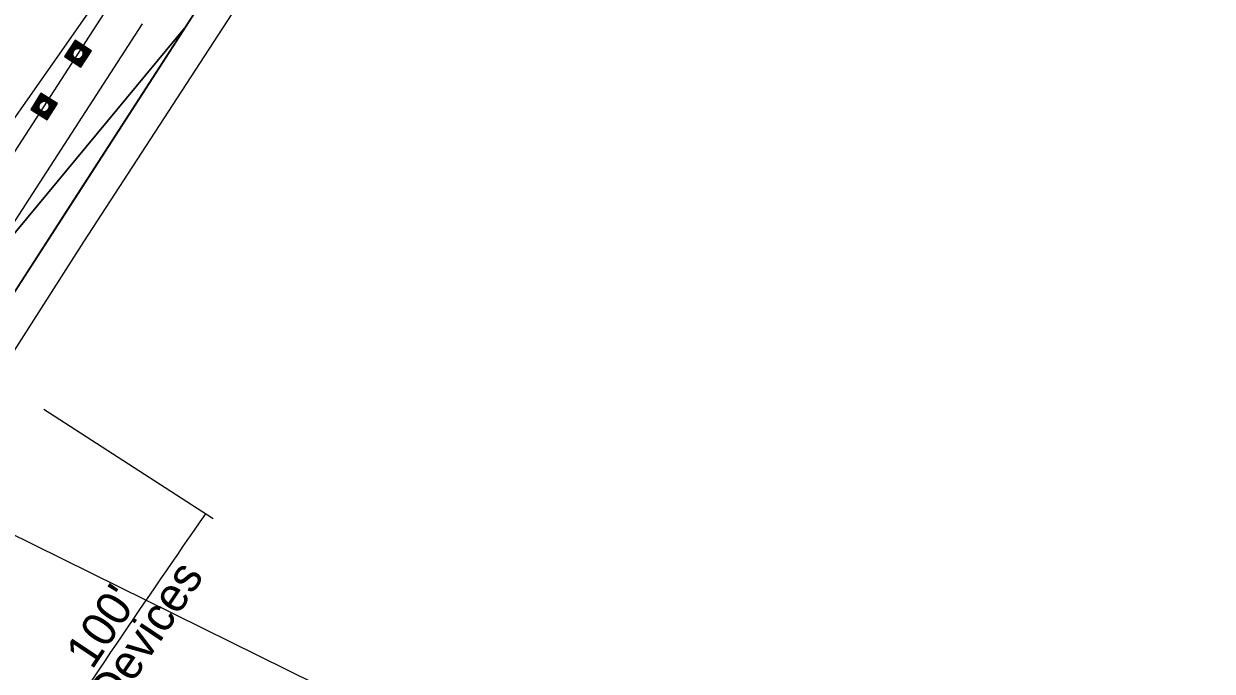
# Model space of a CAD drawing. Extents: x 14104283 to 14128447, y 8633203 to 8671666.
# Drawn here: x 14119316 to 14119692.1, y 8668955.5 to 8669160.5 of the extents above; entities that cross this region are included whole.
import ezdxf

# ---------------------------------------------------------------- set-up
doc = ezdxf.new("R2010")
doc.units = 0
for name, color, linetype in [('dsnCellElements', 7, 'Continuous'), ('dsnNonPlotable', 7, 'Continuous'), ('dsnPaintExistingBrokenLaneLineWhite', 7, 'Continuous'), ('dsnPaintExistingEdgeLineRightWhite', 7, 'Continuous'), ('dsnShadingPaved', 7, 'Continuous'), ('dsnStdLabel', 7, 'Continuous'), ('dsnStgShadingPrevPav', 7, 'Continuous'), ('dsnTapeExistingChannelizingLaneYellow', 7, 'Continuous'), ('dsnTapePlaceChannelizingYellow', 7, 'Continuous'), ('dsnTapeRemoveChannelizingWhite', 7, 'Continuous')]:
    doc.layers.add(name, color=color, linetype=linetype)

msp = doc.modelspace()

# ---------------------------------------------------------------- linework, layer by layer
at = {"layer": 'dsnCellElements'}
for centre in [(14119333.18, 8669150.98), (14119322.46, 8669134.28)]:
    msp.add_circle(centre, 1.65, dxfattribs=at)
at = {"layer": 'dsnNonPlotable'}
msp.add_lwpolyline([(14118092.03, 8667853.71), (14118786.76, 8669258.84), (14119692.14, 8668811.2), (14118997.41, 8667406.07)], close=True, dxfattribs=at)
at = {"layer": 'dsnPaintExistingBrokenLaneLineWhite'}
msp.add_line((14119234.39, 8668975.91), (14119353.59, 8669160.47), dxfattribs=at)
at = {"layer": 'dsnPaintExistingEdgeLineRightWhite'}
for p, q in [((14119329.79, 8669101.47), (14119537.52, 8669423.28)), ((14119259.6, 8668992.73), (14119329.79, 8669101.47))]:
    msp.add_line(p, q, dxfattribs=at)
at = {"layer": 'dsnShadingPaved'}
for p, q in [((14119403.44, 8669259.76), (14119219.81, 8668997.42)), ((14119292.6, 8669088.16), (14119403.44, 8669259.76)), ((14119415.05, 8669233.56), (14119367.38, 8669159.7)), ((14119367.38, 8669159.7), (14119244.61, 8668969.51)), ((14119367.38, 8669159.7), (14119302.7, 8669081.64)), ((14119302.7, 8669081.64), (14119367.38, 8669159.7))]:
    msp.add_line(p, q, dxfattribs=at)
at = {"layer": 'dsnStdLabel'}
msp.add_line((14119375.93, 8669003.77), (14119322.35, 8669038.36), dxfattribs=at)
for points in [[(14119334.06, 8669146.74), (14119337.42, 8669151.86), (14119332.29, 8669155.22), (14119328.94, 8669150.09), (14119334.06, 8669146.74)], [(14119334.06, 8669146.74), (14119337.41, 8669151.86), (14119332.29, 8669155.21), (14119328.94, 8669150.09), (14119334.06, 8669146.74)], [(14119334.06, 8669146.74), (14119337.41, 8669151.86), (14119332.29, 8669155.21), (14119328.94, 8669150.09), (14119334.06, 8669146.74)], [(14119334.1, 8669146.87), (14119337.36, 8669151.85), (14119332.3, 8669155.16), (14119328.99, 8669150.1), (14119334.08, 8669146.77)], [(14119334.09, 8669146.92), (14119337.32, 8669151.84), (14119332.31, 8669155.11), (14119329.04, 8669150.11), (14119334.1, 8669146.8)], [(14119334.08, 8669146.96), (14119337.27, 8669151.83), (14119332.32, 8669155.07), (14119329.08, 8669150.12), (14119334.12, 8669146.82)], [(14119334.08, 8669147.01), (14119337.22, 8669151.82), (14119332.33, 8669155.02), (14119329.13, 8669150.13), (14119334.1, 8669146.87)], [(14119334.07, 8669147.06), (14119337.18, 8669151.81), (14119332.34, 8669154.98), (14119329.17, 8669150.14), (14119334.09, 8669146.92)], [(14119334.06, 8669147.1), (14119337.13, 8669151.8), (14119332.35, 8669154.93), (14119329.22, 8669150.15), (14119334.08, 8669146.96)], [(14119334.05, 8669147.15), (14119337.09, 8669151.79), (14119332.36, 8669154.89), (14119329.26, 8669150.16), (14119334.08, 8669147.01)], [(14119334.04, 8669147.19), (14119337.04, 8669151.78), (14119332.37, 8669154.84), (14119329.31, 8669150.17), (14119334.07, 8669147.06)], [(14119334.03, 8669147.24), (14119337, 8669151.77), (14119332.38, 8669154.79), (14119329.36, 8669150.18), (14119334.06, 8669147.1)], [(14119334.02, 8669147.28), (14119336.95, 8669151.76), (14119332.39, 8669154.75), (14119329.4, 8669150.19), (14119334.05, 8669147.15)], [(14119334.01, 8669147.33), (14119336.9, 8669151.75), (14119332.4, 8669154.7), (14119329.45, 8669150.2), (14119334.04, 8669147.19)], [(14119334, 8669147.38), (14119336.86, 8669151.74), (14119332.41, 8669154.66), (14119329.49, 8669150.21), (14119334.03, 8669147.24)], [(14119333.99, 8669147.42), (14119336.81, 8669151.73), (14119332.42, 8669154.61), (14119329.54, 8669150.22), (14119334.02, 8669147.28)], [(14119333.98, 8669147.47), (14119336.77, 8669151.72), (14119332.43, 8669154.57), (14119329.58, 8669150.23), (14119334.01, 8669147.33)], [(14119333.97, 8669147.51), (14119336.72, 8669151.72), (14119332.44, 8669154.52), (14119329.63, 8669150.23), (14119334, 8669147.38)], [(14119333.96, 8669147.56), (14119336.68, 8669151.71), (14119332.44, 8669154.48), (14119329.68, 8669150.24), (14119333.99, 8669147.42)], [(14119333.95, 8669147.6), (14119336.63, 8669151.7), (14119332.45, 8669154.43), (14119329.72, 8669150.25), (14119333.98, 8669147.47)], [(14119333.94, 8669147.65), (14119336.58, 8669151.69), (14119332.46, 8669154.38), (14119329.77, 8669150.26), (14119333.97, 8669147.51)], [(14119333.93, 8669147.69), (14119336.54, 8669151.68), (14119332.47, 8669154.34), (14119329.81, 8669150.27), (14119333.96, 8669147.56)], [(14119333.92, 8669147.74), (14119336.49, 8669151.67), (14119332.48, 8669154.29), (14119329.86, 8669150.28), (14119333.95, 8669147.6)], [(14119333.91, 8669147.79), (14119336.45, 8669151.66), (14119332.49, 8669154.25), (14119329.9, 8669150.29), (14119333.94, 8669147.65)], [(14119333.9, 8669147.83), (14119336.4, 8669151.65), (14119332.5, 8669154.2), (14119329.95, 8669150.3), (14119333.93, 8669147.69)], [(14119333.89, 8669147.88), (14119336.36, 8669151.64), (14119332.51, 8669154.16), (14119330, 8669150.31), (14119333.92, 8669147.74)], [(14119333.88, 8669147.92), (14119336.31, 8669151.63), (14119332.52, 8669154.11), (14119330.04, 8669150.32), (14119333.91, 8669147.79)], [(14119333.87, 8669147.97), (14119336.26, 8669151.62), (14119332.53, 8669154.06), (14119330.09, 8669150.33), (14119333.9, 8669147.83)], [(14119333.87, 8669148.01), (14119336.22, 8669151.61), (14119332.54, 8669154.02), (14119330.13, 8669150.34), (14119333.89, 8669147.88)], [(14119333.86, 8669148.06), (14119336.17, 8669151.6), (14119332.55, 8669153.97), (14119330.18, 8669150.35), (14119333.88, 8669147.92)], [(14119333.85, 8669148.11), (14119336.13, 8669151.59), (14119332.56, 8669153.93), (14119330.22, 8669150.36), (14119333.87, 8669147.97)], [(14119333.84, 8669148.15), (14119336.08, 8669151.58), (14119332.57, 8669153.88), (14119330.27, 8669150.37), (14119333.87, 8669148.01)], [(14119333.83, 8669148.2), (14119336.04, 8669151.57), (14119332.58, 8669153.84), (14119330.32, 8669150.38), (14119333.86, 8669148.06)], [(14119333.82, 8669148.24), (14119335.99, 8669151.56), (14119332.59, 8669153.79), (14119330.36, 8669150.39), (14119333.85, 8669148.11)], [(14119333.81, 8669148.29), (14119335.94, 8669151.55), (14119332.6, 8669153.74), (14119330.41, 8669150.4), (14119333.84, 8669148.15)], [(14119333.8, 8669148.33), (14119335.9, 8669151.54), (14119332.61, 8669153.7), (14119330.45, 8669150.41), (14119333.83, 8669148.2)], [(14119333.79, 8669148.38), (14119335.85, 8669151.53), (14119332.62, 8669153.65), (14119330.5, 8669150.42), (14119333.82, 8669148.24)], [(14119333.78, 8669148.43), (14119335.81, 8669151.52), (14119332.63, 8669153.61), (14119330.54, 8669150.43), (14119333.81, 8669148.29)], [(14119333.77, 8669148.47), (14119335.76, 8669151.52), (14119332.64, 8669153.56), (14119330.59, 8669150.44), (14119333.8, 8669148.33)], [(14119333.76, 8669148.52), (14119335.72, 8669151.51), (14119332.65, 8669153.52), (14119330.64, 8669150.44), (14119333.79, 8669148.38)], [(14119333.75, 8669148.56), (14119335.67, 8669151.5), (14119332.65, 8669153.47), (14119330.68, 8669150.45), (14119333.78, 8669148.43)], [(14119333.74, 8669148.61), (14119335.62, 8669151.49), (14119332.66, 8669153.42), (14119330.73, 8669150.46), (14119333.77, 8669148.47)], [(14119333.73, 8669148.65), (14119335.58, 8669151.48), (14119332.67, 8669153.38), (14119330.77, 8669150.47), (14119333.76, 8669148.52)], [(14119333.72, 8669148.7), (14119335.53, 8669151.47), (14119332.68, 8669153.33), (14119330.82, 8669150.48), (14119333.75, 8669148.56)], [(14119333.71, 8669148.75), (14119335.49, 8669151.46), (14119332.69, 8669153.29), (14119330.86, 8669150.49), (14119333.74, 8669148.61)], [(14119333.7, 8669148.79), (14119335.44, 8669151.45), (14119332.7, 8669153.24), (14119330.91, 8669150.5), (14119333.73, 8669148.65)], [(14119331.66, 8669151.6), (14119330.95, 8669150.51), (14119332.04, 8669149.8)], [(14119331.62, 8669151.46), (14119331, 8669150.52), (14119331.94, 8669149.91)], [(14119331.59, 8669151.36), (14119331.05, 8669150.53), (14119331.87, 8669149.99)], [(14119331.57, 8669151.27), (14119331.09, 8669150.54), (14119331.82, 8669150.06)], [(14119331.56, 8669151.19), (14119331.14, 8669150.55), (14119331.78, 8669150.13)], [(14119331.55, 8669151.12), (14119331.18, 8669150.56), (14119331.74, 8669150.19)], [(14119331.54, 8669151.05), (14119331.23, 8669150.57), (14119331.71, 8669150.25)], [(14119331.54, 8669150.99), (14119331.27, 8669150.58), (14119331.68, 8669150.31)], [(14119331.54, 8669150.93), (14119331.32, 8669150.59), (14119331.66, 8669150.37)], [(14119331.55, 8669150.87), (14119331.37, 8669150.6), (14119331.64, 8669150.42)], [(14119331.55, 8669150.82), (14119331.41, 8669150.61), (14119331.62, 8669150.47)], [(14119331.56, 8669150.77), (14119331.46, 8669150.62), (14119331.61, 8669150.52)], [(14119331.56, 8669150.72), (14119331.5, 8669150.63), (14119331.59, 8669150.57)], [(14119331.57, 8669150.67), (14119331.55, 8669150.64), (14119331.58, 8669150.61)], [(14119333.8, 8669152.49), (14119332.71, 8669153.2), (14119332, 8669152.11)], [(14119333.66, 8669152.53), (14119332.72, 8669153.15), (14119332.11, 8669152.21)], [(14119333.56, 8669152.56), (14119332.73, 8669153.1), (14119332.19, 8669152.28)], [(14119333.47, 8669152.58), (14119332.74, 8669153.06), (14119332.26, 8669152.33)], [(14119333.39, 8669152.59), (14119332.75, 8669153.01), (14119332.33, 8669152.37)], [(14119333.32, 8669152.6), (14119332.76, 8669152.97), (14119332.39, 8669152.41)], [(14119333.25, 8669152.61), (14119332.77, 8669152.92), (14119332.45, 8669152.44)], [(14119333.19, 8669152.61), (14119332.78, 8669152.88), (14119332.51, 8669152.47)], [(14119333.13, 8669152.61), (14119332.79, 8669152.83), (14119332.57, 8669152.49)], [(14119333.07, 8669152.61), (14119332.8, 8669152.78), (14119332.62, 8669152.51)], [(14119333.02, 8669152.6), (14119332.81, 8669152.74), (14119332.67, 8669152.53)], [(14119332.97, 8669152.6), (14119332.82, 8669152.69), (14119332.72, 8669152.54)], [(14119332.92, 8669152.59), (14119332.83, 8669152.65), (14119332.77, 8669152.56)], [(14119332.87, 8669152.58), (14119332.84, 8669152.6), (14119332.81, 8669152.57)], [(14119334.69, 8669150.35), (14119335.4, 8669151.44), (14119334.31, 8669152.15)], [(14119334.73, 8669150.49), (14119335.35, 8669151.43), (14119334.41, 8669152.04)], [(14119334.76, 8669150.59), (14119335.31, 8669151.42), (14119334.48, 8669151.96)], [(14119334.78, 8669150.68), (14119335.26, 8669151.41), (14119334.53, 8669151.89)], [(14119334.8, 8669150.76), (14119335.21, 8669151.4), (14119334.57, 8669151.82)], [(14119334.8, 8669150.83), (14119335.17, 8669151.39), (14119334.61, 8669151.76)], [(14119334.81, 8669150.9), (14119335.12, 8669151.38), (14119334.64, 8669151.7)], [(14119334.81, 8669150.96), (14119335.08, 8669151.37), (14119334.67, 8669151.64)], [(14119334.81, 8669151.02), (14119335.03, 8669151.36), (14119334.69, 8669151.58)], [(14119334.81, 8669151.08), (14119334.99, 8669151.35), (14119334.71, 8669151.53)], [(14119334.8, 8669151.13), (14119334.94, 8669151.34), (14119334.73, 8669151.48)], [(14119334.8, 8669151.18), (14119334.89, 8669151.33), (14119334.74, 8669151.43)], [(14119334.79, 8669151.23), (14119334.85, 8669151.32), (14119334.76, 8669151.38)], [(14119334.78, 8669151.28), (14119334.8, 8669151.31), (14119334.77, 8669151.34)], [(14119332.55, 8669149.46), (14119333.72, 8669148.7)], [(14119332.69, 8669149.42), (14119333.71, 8669148.75)], [(14119332.79, 8669149.39), (14119333.7, 8669148.79)], [(14119332.88, 8669149.37), (14119333.69, 8669148.84)], [(14119332.96, 8669149.36), (14119333.68, 8669148.88)], [(14119333.03, 8669149.35), (14119333.67, 8669148.93)], [(14119333.1, 8669149.34), (14119333.66, 8669148.97)], [(14119333.16, 8669149.34), (14119333.66, 8669149.02)], [(14119333.22, 8669149.34), (14119333.65, 8669149.07)], [(14119333.28, 8669149.34), (14119333.64, 8669149.11)], [(14119333.33, 8669149.35), (14119333.63, 8669149.16)], [(14119333.38, 8669149.35), (14119333.62, 8669149.2)], [(14119333.43, 8669149.36), (14119333.61, 8669149.25)], [(14119333.48, 8669149.37), (14119333.6, 8669149.29)], [(14119333.6, 8669149.29), (14119333.68, 8669149.42)], [(14119333.61, 8669149.25), (14119333.73, 8669149.44)], [(14119333.62, 8669149.2), (14119333.79, 8669149.46)], [(14119333.63, 8669149.16), (14119333.84, 8669149.48)], [(14119333.64, 8669149.11), (14119333.9, 8669149.51)], [(14119333.65, 8669149.07), (14119333.96, 8669149.54)], [(14119333.66, 8669148.97), (14119334.09, 8669149.62)], [(14119333.66, 8669149.02), (14119334.02, 8669149.58)], [(14119333.67, 8669148.93), (14119334.16, 8669149.67)], [(14119333.68, 8669148.88), (14119334.25, 8669149.74)], [(14119333.69, 8669148.84), (14119334.35, 8669149.84)], [(14119323.45, 8669130.06), (14119326.67, 8669135.27), (14119321.47, 8669138.5), (14119318.24, 8669133.29), (14119323.45, 8669130.06)], [(14119323.44, 8669130.07), (14119326.67, 8669135.27), (14119321.47, 8669138.49), (14119318.24, 8669133.29), (14119323.45, 8669130.07)], [(14119323.44, 8669130.07), (14119326.67, 8669135.27), (14119321.47, 8669138.49), (14119318.25, 8669133.29), (14119323.45, 8669130.07)], [(14119323.49, 8669130.2), (14119326.62, 8669135.26), (14119321.48, 8669138.44), (14119318.29, 8669133.31), (14119323.47, 8669130.1)], [(14119323.48, 8669130.25), (14119326.57, 8669135.25), (14119321.49, 8669138.4), (14119318.34, 8669133.32), (14119323.48, 8669130.13)], [(14119323.46, 8669130.29), (14119326.53, 8669135.24), (14119321.5, 8669138.35), (14119318.39, 8669133.33), (14119323.5, 8669130.15)], [(14119323.45, 8669130.34), (14119326.48, 8669135.23), (14119321.51, 8669138.31), (14119318.43, 8669133.34), (14119323.49, 8669130.2)], [(14119323.44, 8669130.39), (14119326.44, 8669135.22), (14119321.52, 8669138.26), (14119318.48, 8669133.35), (14119323.48, 8669130.25)], [(14119323.43, 8669130.43), (14119326.39, 8669135.21), (14119321.53, 8669138.22), (14119318.52, 8669133.36), (14119323.46, 8669130.29)], [(14119323.42, 8669130.48), (14119326.35, 8669135.19), (14119321.54, 8669138.17), (14119318.57, 8669133.37), (14119323.45, 8669130.34)], [(14119323.41, 8669130.52), (14119326.3, 8669135.18), (14119321.56, 8669138.13), (14119318.61, 8669133.38), (14119323.44, 8669130.39)], [(14119323.4, 8669130.57), (14119326.26, 8669135.17), (14119321.57, 8669138.08), (14119318.66, 8669133.39), (14119323.43, 8669130.43)], [(14119323.39, 8669130.61), (14119326.21, 8669135.16), (14119321.58, 8669138.04), (14119318.7, 8669133.4), (14119323.42, 8669130.48)], [(14119323.38, 8669130.66), (14119326.17, 8669135.15), (14119321.59, 8669137.99), (14119318.75, 8669133.41), (14119323.41, 8669130.52)], [(14119323.37, 8669130.7), (14119326.12, 8669135.14), (14119321.6, 8669137.94), (14119318.79, 8669133.42), (14119323.4, 8669130.57)], [(14119323.36, 8669130.75), (14119326.07, 8669135.13), (14119321.61, 8669137.9), (14119318.84, 8669133.43), (14119323.39, 8669130.61)], [(14119323.35, 8669130.79), (14119326.03, 8669135.12), (14119321.62, 8669137.85), (14119318.89, 8669133.44), (14119323.38, 8669130.66)], [(14119323.34, 8669130.84), (14119325.98, 8669135.11), (14119321.63, 8669137.81), (14119318.93, 8669133.45), (14119323.37, 8669130.7)], [(14119323.33, 8669130.89), (14119325.94, 8669135.1), (14119321.64, 8669137.76), (14119318.98, 8669133.47), (14119323.36, 8669130.75)], [(14119323.32, 8669130.93), (14119325.89, 8669135.09), (14119321.65, 8669137.72), (14119319.02, 8669133.48), (14119323.35, 8669130.79)], [(14119323.3, 8669130.98), (14119325.85, 8669135.08), (14119321.66, 8669137.67), (14119319.07, 8669133.49), (14119323.34, 8669130.84)], [(14119323.29, 8669131.02), (14119325.8, 8669135.07), (14119321.67, 8669137.63), (14119319.11, 8669133.5), (14119323.33, 8669130.89)], [(14119323.28, 8669131.07), (14119325.76, 8669135.06), (14119321.68, 8669137.58), (14119319.16, 8669133.51), (14119323.32, 8669130.93)], [(14119323.27, 8669131.11), (14119325.71, 8669135.05), (14119321.69, 8669137.54), (14119319.2, 8669133.52), (14119323.3, 8669130.98)], [(14119323.26, 8669131.16), (14119325.67, 8669135.03), (14119321.7, 8669137.49), (14119319.25, 8669133.53), (14119323.29, 8669131.02)], [(14119323.25, 8669131.2), (14119325.62, 8669135.02), (14119321.72, 8669137.44), (14119319.29, 8669133.54), (14119323.28, 8669131.07)], [(14119323.24, 8669131.25), (14119325.57, 8669135.01), (14119321.73, 8669137.4), (14119319.34, 8669133.55), (14119323.27, 8669131.11)], [(14119323.23, 8669131.29), (14119325.53, 8669135), (14119321.74, 8669137.35), (14119319.39, 8669133.56), (14119323.26, 8669131.16)], [(14119323.22, 8669131.34), (14119325.48, 8669134.99), (14119321.75, 8669137.31), (14119319.43, 8669133.57), (14119323.25, 8669131.2)], [(14119323.21, 8669131.38), (14119325.44, 8669134.98), (14119321.76, 8669137.26), (14119319.48, 8669133.58), (14119323.24, 8669131.25)], [(14119323.2, 8669131.43), (14119325.39, 8669134.97), (14119321.77, 8669137.22), (14119319.52, 8669133.59), (14119323.23, 8669131.29)], [(14119323.19, 8669131.48), (14119325.35, 8669134.96), (14119321.78, 8669137.17), (14119319.57, 8669133.6), (14119323.22, 8669131.34)], [(14119323.18, 8669131.52), (14119325.3, 8669134.95), (14119321.79, 8669137.13), (14119319.61, 8669133.61), (14119323.21, 8669131.38)], [(14119323.17, 8669131.57), (14119325.26, 8669134.94), (14119321.8, 8669137.08), (14119319.66, 8669133.63), (14119323.2, 8669131.43)], [(14119323.16, 8669131.61), (14119325.21, 8669134.93), (14119321.81, 8669137.04), (14119319.7, 8669133.64), (14119323.19, 8669131.48)], [(14119323.14, 8669131.66), (14119325.17, 8669134.92), (14119321.82, 8669136.99), (14119319.75, 8669133.65), (14119323.18, 8669131.52)], [(14119323.13, 8669131.7), (14119325.12, 8669134.91), (14119321.83, 8669136.94), (14119319.79, 8669133.66), (14119323.17, 8669131.57)], [(14119323.12, 8669131.75), (14119325.08, 8669134.9), (14119321.84, 8669136.9), (14119319.84, 8669133.67), (14119323.16, 8669131.61)], [(14119323.11, 8669131.79), (14119325.03, 8669134.89), (14119321.85, 8669136.85), (14119319.89, 8669133.68), (14119323.14, 8669131.66)], [(14119323.1, 8669131.84), (14119324.98, 8669134.87), (14119321.86, 8669136.81), (14119319.93, 8669133.69), (14119323.13, 8669131.7)], [(14119323.09, 8669131.88), (14119324.94, 8669134.86), (14119321.88, 8669136.76), (14119319.98, 8669133.7), (14119323.12, 8669131.75)], [(14119323.08, 8669131.93), (14119324.89, 8669134.85), (14119321.89, 8669136.72), (14119320.02, 8669133.71), (14119323.11, 8669131.79)], [(14119323.07, 8669131.98), (14119324.85, 8669134.84), (14119321.9, 8669136.67), (14119320.07, 8669133.72), (14119323.1, 8669131.84)], [(14119323.06, 8669132.02), (14119324.8, 8669134.83), (14119321.91, 8669136.63), (14119320.11, 8669133.73), (14119323.09, 8669131.88)], [(14119323.05, 8669132.07), (14119324.76, 8669134.82), (14119321.92, 8669136.58), (14119320.16, 8669133.74), (14119323.08, 8669131.93)], [(14119323.04, 8669132.11), (14119324.71, 8669134.81), (14119321.93, 8669136.54), (14119320.2, 8669133.75), (14119323.07, 8669131.98)], [(14119323.04, 8669135.81), (14119321.94, 8669136.49), (14119321.26, 8669135.39)], [(14119322.91, 8669135.85), (14119321.95, 8669136.45), (14119321.36, 8669135.49)], [(14119322.8, 8669135.88), (14119321.96, 8669136.4), (14119321.44, 8669135.56)], [(14119322.71, 8669135.9), (14119321.97, 8669136.35), (14119321.51, 8669135.61)], [(14119322.63, 8669135.91), (14119321.98, 8669136.31), (14119321.58, 8669135.66)], [(14119322.56, 8669135.91), (14119321.99, 8669136.26), (14119321.64, 8669135.7)], [(14119322.49, 8669135.91), (14119322, 8669136.22), (14119321.7, 8669135.73)], [(14119322.43, 8669135.92), (14119322.01, 8669136.17), (14119321.76, 8669135.76)], [(14119322.37, 8669135.91), (14119322.02, 8669136.13), (14119321.81, 8669135.78)], [(14119322.31, 8669135.91), (14119322.04, 8669136.08), (14119321.86, 8669135.8)], [(14119322.26, 8669135.9), (14119322.05, 8669136.04), (14119321.91, 8669135.82)], [(14119322.21, 8669135.9), (14119322.06, 8669135.99), (14119321.96, 8669135.84)], [(14119322.16, 8669135.89), (14119322.07, 8669135.95), (14119322.01, 8669135.85)], [(14119322.11, 8669135.88), (14119322.08, 8669135.9), (14119322.06, 8669135.87)], [(14119320.93, 8669134.87), (14119320.25, 8669133.76), (14119321.35, 8669133.08)], [(14119320.89, 8669134.73), (14119320.29, 8669133.77), (14119321.25, 8669133.18)], [(14119320.86, 8669134.63), (14119320.34, 8669133.78), (14119321.18, 8669133.26)], [(14119320.84, 8669134.54), (14119320.38, 8669133.8), (14119321.12, 8669133.34)], [(14119320.83, 8669134.46), (14119320.43, 8669133.81), (14119321.08, 8669133.4)], [(14119320.83, 8669134.38), (14119320.48, 8669133.82), (14119321.04, 8669133.47)], [(14119320.82, 8669134.32), (14119320.52, 8669133.83), (14119321.01, 8669133.52)], [(14119320.82, 8669134.25), (14119320.57, 8669133.84), (14119320.98, 8669133.58)], [(14119320.83, 8669134.19), (14119320.61, 8669133.85), (14119320.96, 8669133.63)], [(14119320.83, 8669134.14), (14119320.66, 8669133.86), (14119320.94, 8669133.69)], [(14119320.84, 8669134.08), (14119320.7, 8669133.87), (14119320.92, 8669133.74)], [(14119320.84, 8669134.03), (14119320.75, 8669133.88), (14119320.9, 8669133.79)], [(14119320.85, 8669133.98), (14119320.79, 8669133.89), (14119320.89, 8669133.83)], [(14119320.86, 8669133.94), (14119320.84, 8669133.9), (14119320.87, 8669133.88)], [(14119321.87, 8669132.76), (14119323.06, 8669132.02)], [(14119322.01, 8669132.71), (14119323.05, 8669132.07)], [(14119322.11, 8669132.68), (14119323.04, 8669132.11)], [(14119322.2, 8669132.67), (14119323.03, 8669132.16)], [(14119322.28, 8669132.66), (14119323.02, 8669132.2)], [(14119322.36, 8669132.65), (14119323.01, 8669132.25)], [(14119322.42, 8669132.65), (14119323, 8669132.29)], [(14119322.49, 8669132.65), (14119322.99, 8669132.34)], [(14119322.54, 8669132.65), (14119322.97, 8669132.38)], [(14119322.6, 8669132.65), (14119322.96, 8669132.43)], [(14119322.65, 8669132.66), (14119322.95, 8669132.48)], [(14119322.71, 8669132.67), (14119322.94, 8669132.52)], [(14119322.76, 8669132.68), (14119322.93, 8669132.57)], [(14119322.8, 8669132.69), (14119322.92, 8669132.61)], [(14119322.92, 8669132.61), (14119323, 8669132.74)], [(14119322.93, 8669132.57), (14119323.05, 8669132.76)], [(14119322.94, 8669132.52), (14119323.1, 8669132.78)], [(14119322.95, 8669132.48), (14119323.16, 8669132.81)], [(14119322.96, 8669132.43), (14119323.21, 8669132.83)], [(14119322.97, 8669132.38), (14119323.27, 8669132.87)], [(14119322.99, 8669132.34), (14119323.34, 8669132.9)], [(14119323, 8669132.29), (14119323.4, 8669132.95)], [(14119323.01, 8669132.25), (14119323.48, 8669133)], [(14119323.02, 8669132.2), (14119323.56, 8669133.07)], [(14119323.03, 8669132.16), (14119323.66, 8669133.17)], [(14119323.98, 8669133.7), (14119324.67, 8669134.8), (14119323.56, 8669135.48)], [(14119324.03, 8669133.83), (14119324.62, 8669134.79), (14119323.66, 8669135.38)], [(14119324.05, 8669133.94), (14119324.58, 8669134.78), (14119323.74, 8669135.3)], [(14119324.07, 8669134.03), (14119324.53, 8669134.77), (14119323.79, 8669135.23)], [(14119324.08, 8669134.11), (14119324.48, 8669134.76), (14119323.83, 8669135.16)], [(14119324.09, 8669134.18), (14119324.44, 8669134.75), (14119323.87, 8669135.1)], [(14119324.09, 8669134.25), (14119324.39, 8669134.74), (14119323.9, 8669135.04)], [(14119324.09, 8669134.31), (14119324.35, 8669134.73), (14119323.93, 8669134.98)], [(14119324.09, 8669134.37), (14119324.3, 8669134.71), (14119323.96, 8669134.93)], [(14119324.08, 8669134.43), (14119324.26, 8669134.7), (14119323.98, 8669134.88)], [(14119324.08, 8669134.48), (14119324.21, 8669134.69), (14119324, 8669134.83)], [(14119324.07, 8669134.53), (14119324.17, 8669134.68), (14119324.01, 8669134.78)], [(14119324.06, 8669134.58), (14119324.12, 8669134.67), (14119324.03, 8669134.73)], [(14119324.05, 8669134.63), (14119324.08, 8669134.66), (14119324.04, 8669134.68)]]:
    msp.add_lwpolyline(points, dxfattribs=at)
msp.add_arc((14123077.55, 8666441.06), 4505.04, 145.30555, 146.57768, dxfattribs=at)
at = {"layer": 'dsnStgShadingPrevPav'}
msp.add_lwpolyline([(14119455.82, 8669289.13), (14119447.45, 8669266.1), (14119424.62, 8669230.68), (14119396.25, 8669185.73), (14119365.96, 8669139.11), (14119334.97, 8669091.45), (14119304.91, 8669044.51), (14119267.2, 8668986.39), (14119235.59, 8668937.49), (14119203.77, 8668887.79), (14119172.82, 8668837.38)], dxfattribs=at)
at = {"layer": 'dsnTapeExistingChannelizingLaneYellow'}
msp.add_line((14119403.44, 8669259.76), (14119219.81, 8668997.42), dxfattribs=at)
at = {"layer": 'dsnTapePlaceChannelizingYellow'}
msp.add_line((14119292.6, 8669088.16), (14119403.44, 8669259.76), dxfattribs=at)
at = {"layer": 'dsnTapeRemoveChannelizingWhite'}
msp.add_line((14119302.7, 8669081.64), (14119367.38, 8669159.7), dxfattribs=at)

# ---------------------------------------------------------------- texts
at = {"layer": 'dsnStdLabel'}
for s, p in [('5 Devices', (14119337.97, 8668932.91)), ("100'", (14119337.65, 8668955.7))]:
    msp.add_text(s, height=10.8, rotation=56.1547, dxfattribs=at).set_placement(p)

doc.saveas('drawing.dxf')
